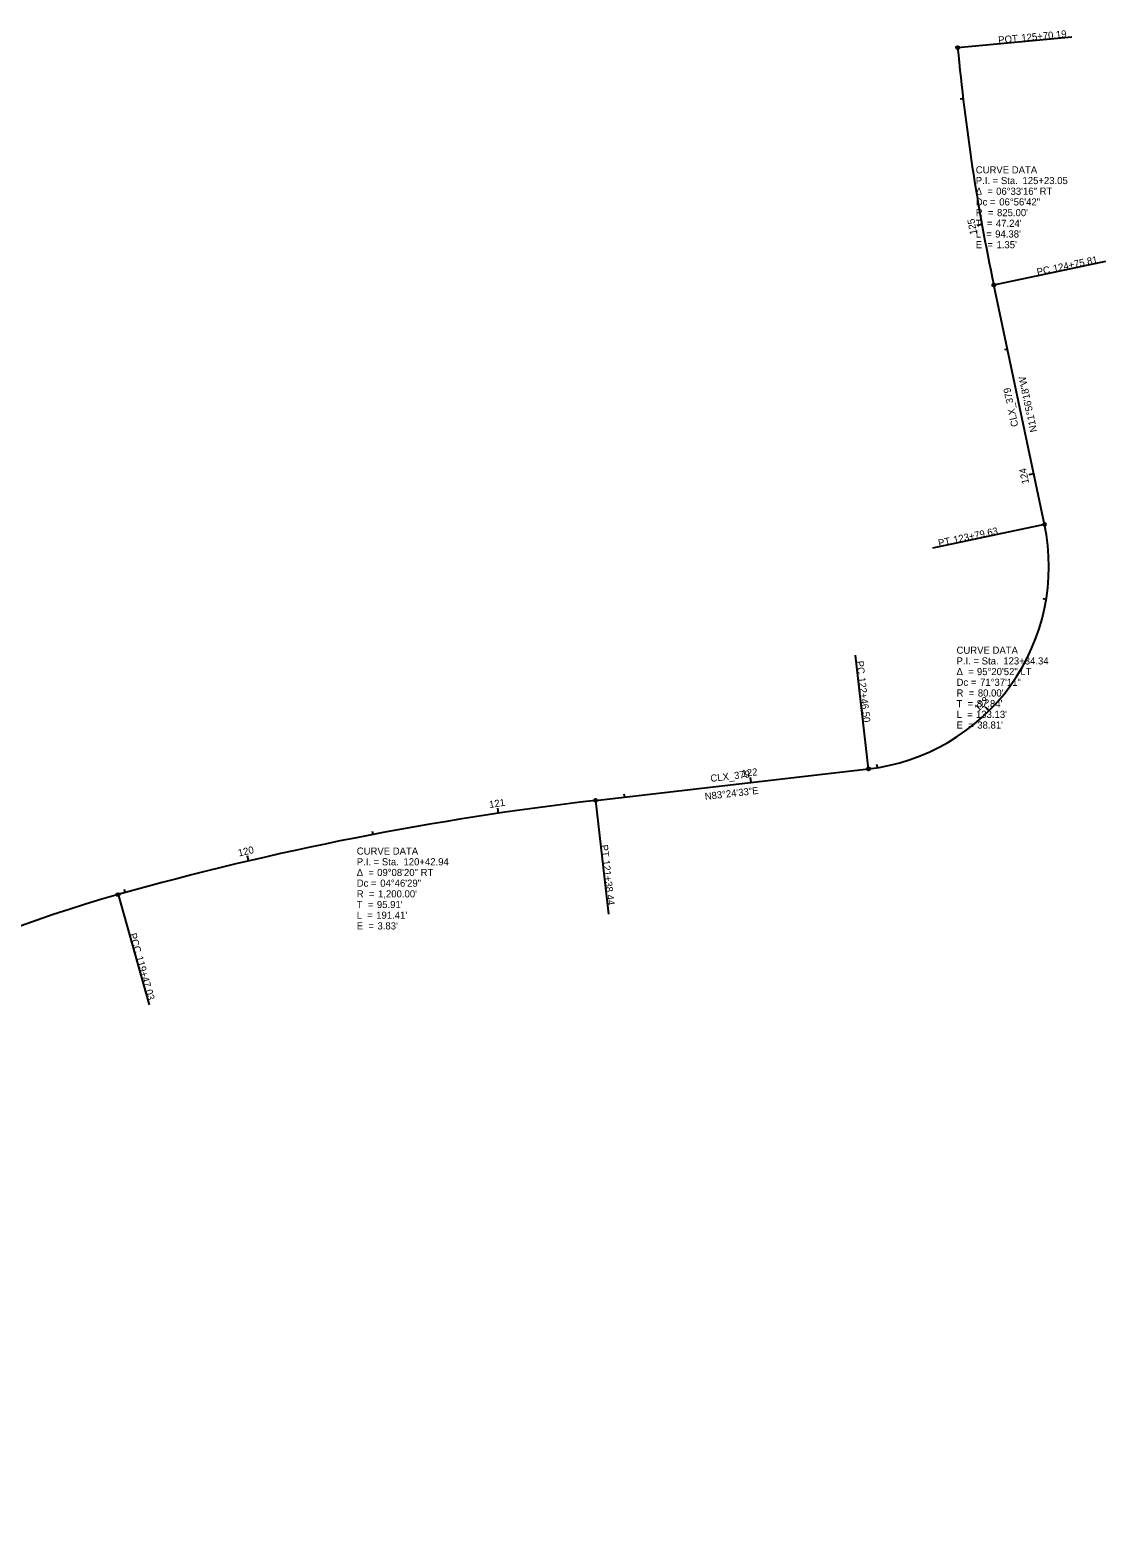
# Model space of a CAD drawing. Extents: x 2325404 to 2326256, y 693508 to 694271.
# Drawn here: x 2325834 to 2326256, y 693678 to 694271 of the extents above; entities that cross this region are included whole.
import ezdxf

# ---------------------------------------------------------------- set-up
doc = ezdxf.new("R2010")
doc.units = 0
for name, color, linetype in [('GE_X_Alignment', 7, 'Continuous'), ('GE_X_Alignment_1000_Curve_Data', 7, 'Continuous'), ('GE_X_Alignment_1000_Stations', 7, 'Continuous'), ('GE_X_Alignment_100_Curve_Data', 7, 'Continuous'), ('GE_X_Alignment_100_Stations', 7, 'Continuous'), ('GE_X_Alignment_500_Curve_Data', 7, 'Continuous'), ('GE_X_Alignment_500_Stations', 7, 'Continuous')]:
    doc.layers.add(name, color=color, linetype=linetype)

msp = doc.modelspace()

# ---------------------------------------------------------------- linework, layer by layer
at = {"layer": 'GE_X_Alignment'}
for p, q in [((2326232.19, 694076.32), (2326212.3, 694170.42)), ((2326055.76, 693967.89), (2326163.11, 693980.3))]:
    msp.add_line(p, q, dxfattribs=at)
for centre, radius, start, end in [((2327019.45, 694341.07), 825, 185.38408, 191.93842), ((2326153.93, 694059.77), 80, 276.59071, 11.93842), ((2326193.49, 692775.82), 1200, 96.59071, 105.72963), ((2326017.28, 693401.48), 550, 105.72963, 149.7973)]:
    msp.add_arc(centre, radius, start, end, dxfattribs=at)
at = {"layer": 'GE_X_Alignment_1000_Stations'}
for p, q in [((2326198.09, 694263.66), (2326242.9, 694267.89)), ((2326207.64, 694194.15), (2326206.46, 694193.94)), ((2326212.3, 694170.42), (2326256.33, 694179.72)), ((2326232.19, 694076.32), (2326188.17, 694067.01)), ((2326163.11, 693980.3), (2326157.94, 694025)), ((2326055.76, 693967.89), (2326060.93, 693923.19)), ((2325919.46, 693944.11), (2325919, 693946.06)), ((2325868.17, 693930.88), (2325880.37, 693887.57))]:
    msp.add_line(p, q, dxfattribs=at)
for centre in [(2326198.09, 694263.66), (2326212.3, 694170.42), (2326232.19, 694076.32), (2326163.11, 693980.3), (2326055.76, 693967.89), (2325868.17, 693930.88)]:
    msp.add_circle(centre, 0.6, dxfattribs=at)
at = {"layer": 'GE_X_Alignment_100_Stations'}
for p, q in [((2326198.09, 694263.66), (2326242.9, 694267.89)), ((2326200.23, 694243.59), (2326199.04, 694243.45)), ((2326207.64, 694194.15), (2326205.67, 694193.8)), ((2326212.3, 694170.42), (2326256.33, 694179.72)), ((2326217.64, 694145.16), (2326216.46, 694144.92)), ((2326227.98, 694096.25), (2326226.02, 694095.83)), ((2326232.19, 694076.32), (2326188.17, 694067.01)), ((2326232.88, 694046.86), (2326231.69, 694047.06)), ((2326163.11, 693980.3), (2326157.94, 694025)), ((2326210.4, 694003.11), (2326208.99, 694004.52)), ((2326166.58, 693980.77), (2326166.39, 693981.96)), ((2326116.92, 693974.96), (2326116.69, 693976.94)), ((2326055.76, 693967.89), (2326060.93, 693923.19)), ((2326067.25, 693969.22), (2326067.11, 693970.41)), ((2326017.65, 693962.87), (2326017.36, 693964.85)), ((2325968.36, 693954.52), (2325968.13, 693955.69)), ((2325919.46, 693944.11), (2325919, 693946.06)), ((2325871.03, 693931.69), (2325870.71, 693932.84)), ((2325868.17, 693930.88), (2325880.37, 693887.57))]:
    msp.add_line(p, q, dxfattribs=at)
for centre in [(2326198.09, 694263.66), (2326212.3, 694170.42), (2326232.19, 694076.32), (2326163.11, 693980.3), (2326055.76, 693967.89), (2325868.17, 693930.88)]:
    msp.add_circle(centre, 0.6, dxfattribs=at)
at = {"layer": 'GE_X_Alignment_500_Stations'}
for p, q in [((2326198.09, 694263.66), (2326242.9, 694267.89)), ((2326207.64, 694194.15), (2326205.67, 694193.8)), ((2326212.3, 694170.42), (2326256.33, 694179.72)), ((2326227.98, 694096.25), (2326226.81, 694096)), ((2326232.19, 694076.32), (2326188.17, 694067.01)), ((2326163.11, 693980.3), (2326157.94, 694025)), ((2326210.4, 694003.11), (2326209.56, 694003.96)), ((2326116.92, 693974.96), (2326116.78, 693976.15)), ((2326055.76, 693967.89), (2326060.93, 693923.19)), ((2326017.65, 693962.87), (2326017.48, 693964.06)), ((2325919.46, 693944.11), (2325919, 693946.06)), ((2325868.17, 693930.88), (2325880.37, 693887.57))]:
    msp.add_line(p, q, dxfattribs=at)
for centre in [(2326198.09, 694263.66), (2326212.3, 694170.42), (2326232.19, 694076.32), (2326163.11, 693980.3), (2326055.76, 693967.89), (2325868.17, 693930.88)]:
    msp.add_circle(centre, 0.6, dxfattribs=at)

# ---------------------------------------------------------------- texts
at = {"layer": 'GE_X_Alignment_1000_Curve_Data'}
for s, p in [('CURVE DATA', (2326205.2, 694214.24)), ('P.I. = Sta. ', (2326205.2, 694210.04)), ('125+23.05', (2326223.57, 694210.04)), ('Δ  = ', (2326205.2, 694205.84)), ('Dc = ', (2326205.2, 694201.64)), ('06°33\'16" RT', (2326213.22, 694205.84)), ('06°56\'42"', (2326214.44, 694201.64)), ('R  = ', (2326205.2, 694197.44)), ("825.00'", (2326213.56, 694197.44)), ('T  = ', (2326205.2, 694193.24)), ("94.38'", (2326212.84, 694189.04)), ("47.24'", (2326213.13, 694193.24)), ('L  = ', (2326205.2, 694189.04)), ('E  = ', (2326205.2, 694184.84)), ("1.35'", (2326213.35, 694184.84)), ('CURVE DATA', (2326197.65, 694025.51)), ('P.I. = Sta. ', (2326197.65, 694021.31)), ('123+34.34', (2326216.02, 694021.31)), ('Δ  = ', (2326197.65, 694017.11)), ('Dc = ', (2326197.65, 694012.91)), ('95°20\'52" LT', (2326205.67, 694017.11)), ('71°37\'11"', (2326206.89, 694012.91)), ('R  = ', (2326197.65, 694008.71)), ("80.00'", (2326206.02, 694008.71)), ('T  = ', (2326197.65, 694004.51)), ('L  = ', (2326197.65, 694000.31)), ("133.13'", (2326205.3, 694000.31)), ("87.84'", (2326205.58, 694004.51)), ('E  = ', (2326197.65, 693996.11)), ("38.81'", (2326205.8, 693996.11)), ('CURVE DATA', (2325961.97, 693946.59)), ('P.I. = Sta. ', (2325961.97, 693942.39)), ('120+42.94', (2325980.34, 693942.39)), ('Δ  = ', (2325961.97, 693938.19)), ('09°08\'20" RT', (2325969.99, 693938.19)), ('Dc = ', (2325961.97, 693933.99)), ('R  = ', (2325961.97, 693929.79)), ("1,200.00'", (2325970.34, 693929.79)), ('04°46\'29"', (2325971.21, 693933.99)), ('T  = ', (2325961.97, 693925.59)), ("95.91'", (2325969.9, 693925.59)), ('L  = ', (2325961.97, 693921.39)), ('E  = ', (2325961.97, 693917.19)), ("191.41'", (2325969.61, 693921.39)), ("3.83'", (2325970.12, 693917.19))]:
    msp.add_text(s, height=2.8, dxfattribs=at).set_placement(p)
at = {"layer": 'GE_X_Alignment_1000_Stations'}
for s, rotation, p in [('125+70.19', 5.38408, (2326223.26, 694266.08)), ('POT', 5.38408, (2326214.17, 694265.23)), ('124+75.81', 11.93842, (2326235.88, 694175.45)), ('PC', 11.93842, (2326229.5, 694174.1)), ('N11°56\'18"W', 101.93842, (2326229.37, 694112.89)), ('CLX_379', 101.93842, (2326221.97, 694114.98)), ('123+79.63', 11.93842, (2326196.71, 694068.86)), ('PT', 11.93842, (2326190.76, 694067.6)), ('PC', 276.59071, (2326158.27, 694022.59)), ('122+46.50', 276.59071, (2326159.02, 694016.12)), ('CLX_379', 6.59071, (2326101.11, 693975.15)), ('N83°24\'33"E', 6.59071, (2326098.88, 693968.04)), ('120', 13.20066, (2325915.68, 693945.84)), ('PT', 276.59071, (2326057.84, 693950.33)), ('121+38.44', 276.59071, (2326058.54, 693944.28)), ('PCC', 285.72963, (2325872.6, 693915.33)), ('119+47.03', 285.72963, (2325875.14, 693906.33))]:
    msp.add_text(s, height=2.8, rotation=rotation, dxfattribs=at).set_placement(p)
at = {"layer": 'GE_X_Alignment_100_Curve_Data'}
for s, p in [('CURVE DATA', (2326205.2, 694214.24)), ('P.I. = Sta. ', (2326205.2, 694210.04)), ('125+23.05', (2326223.57, 694210.04)), ('Δ  = ', (2326205.2, 694205.84)), ('Dc = ', (2326205.2, 694201.64)), ('06°33\'16" RT', (2326213.22, 694205.84)), ('06°56\'42"', (2326214.44, 694201.64)), ('R  = ', (2326205.2, 694197.44)), ("825.00'", (2326213.56, 694197.44)), ('T  = ', (2326205.2, 694193.24)), ("94.38'", (2326212.84, 694189.04)), ("47.24'", (2326213.13, 694193.24)), ('L  = ', (2326205.2, 694189.04)), ('E  = ', (2326205.2, 694184.84)), ("1.35'", (2326213.35, 694184.84)), ('CURVE DATA', (2326197.65, 694025.51)), ('P.I. = Sta. ', (2326197.65, 694021.31)), ('123+34.34', (2326216.02, 694021.31)), ('Δ  = ', (2326197.65, 694017.11)), ('Dc = ', (2326197.65, 694012.91)), ('95°20\'52" LT', (2326205.67, 694017.11)), ('71°37\'11"', (2326206.89, 694012.91)), ('R  = ', (2326197.65, 694008.71)), ("80.00'", (2326206.02, 694008.71)), ('T  = ', (2326197.65, 694004.51)), ('L  = ', (2326197.65, 694000.31)), ("133.13'", (2326205.3, 694000.31)), ("87.84'", (2326205.58, 694004.51)), ('E  = ', (2326197.65, 693996.11)), ("38.81'", (2326205.8, 693996.11)), ('CURVE DATA', (2325961.97, 693946.59)), ('P.I. = Sta. ', (2325961.97, 693942.39)), ('120+42.94', (2325980.34, 693942.39)), ('Δ  = ', (2325961.97, 693938.19)), ('09°08\'20" RT', (2325969.99, 693938.19)), ('Dc = ', (2325961.97, 693933.99)), ('R  = ', (2325961.97, 693929.79)), ("1,200.00'", (2325970.34, 693929.79)), ('04°46\'29"', (2325971.21, 693933.99)), ('T  = ', (2325961.97, 693925.59)), ("95.91'", (2325969.9, 693925.59)), ('L  = ', (2325961.97, 693921.39)), ('E  = ', (2325961.97, 693917.19)), ("191.41'", (2325969.61, 693921.39)), ("3.83'", (2325970.12, 693917.19))]:
    msp.add_text(s, height=2.8, dxfattribs=at).set_placement(p)
at = {"layer": 'GE_X_Alignment_100_Stations'}
for s, rotation, p in [('125+70.19', 5.38408, (2326223.26, 694266.08)), ('POT', 5.38408, (2326214.17, 694265.23)), ('125', 100.25843, (2326205.72, 694190.46)), ('124+75.81', 11.93842, (2326235.88, 694175.45)), ('PC', 11.93842, (2326229.5, 694174.1)), ('N11°56\'18"W', 101.93842, (2326229.37, 694112.89)), ('CLX_379', 101.93842, (2326221.97, 694114.98)), ('124', 101.93842, (2326226.2, 694092.56)), ('123+79.63', 11.93842, (2326196.71, 694068.86)), ('PT', 11.93842, (2326190.76, 694067.6)), ('PC', 276.59071, (2326158.27, 694022.59)), ('122+46.50', 276.59071, (2326159.02, 694016.12)), ('123', 44.90792, (2326206.29, 694002.61)), ('CLX_379', 6.59071, (2326101.11, 693975.15)), ('122', 6.59071, (2326113.38, 693977.07)), ('N83°24\'33"E', 6.59071, (2326098.88, 693968.04)), ('121', 8.42601, (2326014.21, 693964.89)), ('120', 13.20066, (2325915.68, 693945.84)), ('PT', 276.59071, (2326057.84, 693950.33)), ('121+38.44', 276.59071, (2326058.54, 693944.28)), ('PCC', 285.72963, (2325872.6, 693915.33)), ('119+47.03', 285.72963, (2325875.14, 693906.33))]:
    msp.add_text(s, height=2.8, rotation=rotation, dxfattribs=at).set_placement(p)
at = {"layer": 'GE_X_Alignment_500_Curve_Data'}
for s, p in [('CURVE DATA', (2326205.2, 694214.24)), ('P.I. = Sta. ', (2326205.2, 694210.04)), ('125+23.05', (2326223.57, 694210.04)), ('Δ  = ', (2326205.2, 694205.84)), ('Dc = ', (2326205.2, 694201.64)), ('06°33\'16" RT', (2326213.22, 694205.84)), ('06°56\'42"', (2326214.44, 694201.64)), ('R  = ', (2326205.2, 694197.44)), ("825.00'", (2326213.56, 694197.44)), ('T  = ', (2326205.2, 694193.24)), ("94.38'", (2326212.84, 694189.04)), ("47.24'", (2326213.13, 694193.24)), ('L  = ', (2326205.2, 694189.04)), ('E  = ', (2326205.2, 694184.84)), ("1.35'", (2326213.35, 694184.84)), ('CURVE DATA', (2326197.65, 694025.51)), ('P.I. = Sta. ', (2326197.65, 694021.31)), ('123+34.34', (2326216.02, 694021.31)), ('Δ  = ', (2326197.65, 694017.11)), ('Dc = ', (2326197.65, 694012.91)), ('95°20\'52" LT', (2326205.67, 694017.11)), ('71°37\'11"', (2326206.89, 694012.91)), ('R  = ', (2326197.65, 694008.71)), ("80.00'", (2326206.02, 694008.71)), ('T  = ', (2326197.65, 694004.51)), ('L  = ', (2326197.65, 694000.31)), ("133.13'", (2326205.3, 694000.31)), ("87.84'", (2326205.58, 694004.51)), ('E  = ', (2326197.65, 693996.11)), ("38.81'", (2326205.8, 693996.11)), ('CURVE DATA', (2325961.97, 693946.59)), ('P.I. = Sta. ', (2325961.97, 693942.39)), ('120+42.94', (2325980.34, 693942.39)), ('Δ  = ', (2325961.97, 693938.19)), ('09°08\'20" RT', (2325969.99, 693938.19)), ('Dc = ', (2325961.97, 693933.99)), ('R  = ', (2325961.97, 693929.79)), ("1,200.00'", (2325970.34, 693929.79)), ('04°46\'29"', (2325971.21, 693933.99)), ('T  = ', (2325961.97, 693925.59)), ("95.91'", (2325969.9, 693925.59)), ('L  = ', (2325961.97, 693921.39)), ('E  = ', (2325961.97, 693917.19)), ("191.41'", (2325969.61, 693921.39)), ("3.83'", (2325970.12, 693917.19))]:
    msp.add_text(s, height=2.8, dxfattribs=at).set_placement(p)
at = {"layer": 'GE_X_Alignment_500_Stations'}
for s, rotation, p in [('125+70.19', 5.38408, (2326223.26, 694266.08)), ('POT', 5.38408, (2326214.17, 694265.23)), ('125', 100.25843, (2326205.72, 694190.46)), ('124+75.81', 11.93842, (2326235.88, 694175.45)), ('PC', 11.93842, (2326229.5, 694174.1)), ('N11°56\'18"W', 101.93842, (2326229.37, 694112.89)), ('CLX_379', 101.93842, (2326221.97, 694114.98)), ('123+79.63', 11.93842, (2326196.71, 694068.86)), ('PT', 11.93842, (2326190.76, 694067.6)), ('PC', 276.59071, (2326158.27, 694022.59)), ('122+46.50', 276.59071, (2326159.02, 694016.12)), ('CLX_379', 6.59071, (2326101.11, 693975.15)), ('N83°24\'33"E', 6.59071, (2326098.88, 693968.04)), ('120', 13.20066, (2325915.68, 693945.84)), ('PT', 276.59071, (2326057.84, 693950.33)), ('121+38.44', 276.59071, (2326058.54, 693944.28)), ('PCC', 285.72963, (2325872.6, 693915.33)), ('119+47.03', 285.72963, (2325875.14, 693906.33))]:
    msp.add_text(s, height=2.8, rotation=rotation, dxfattribs=at).set_placement(p)

doc.saveas('drawing.dxf')
